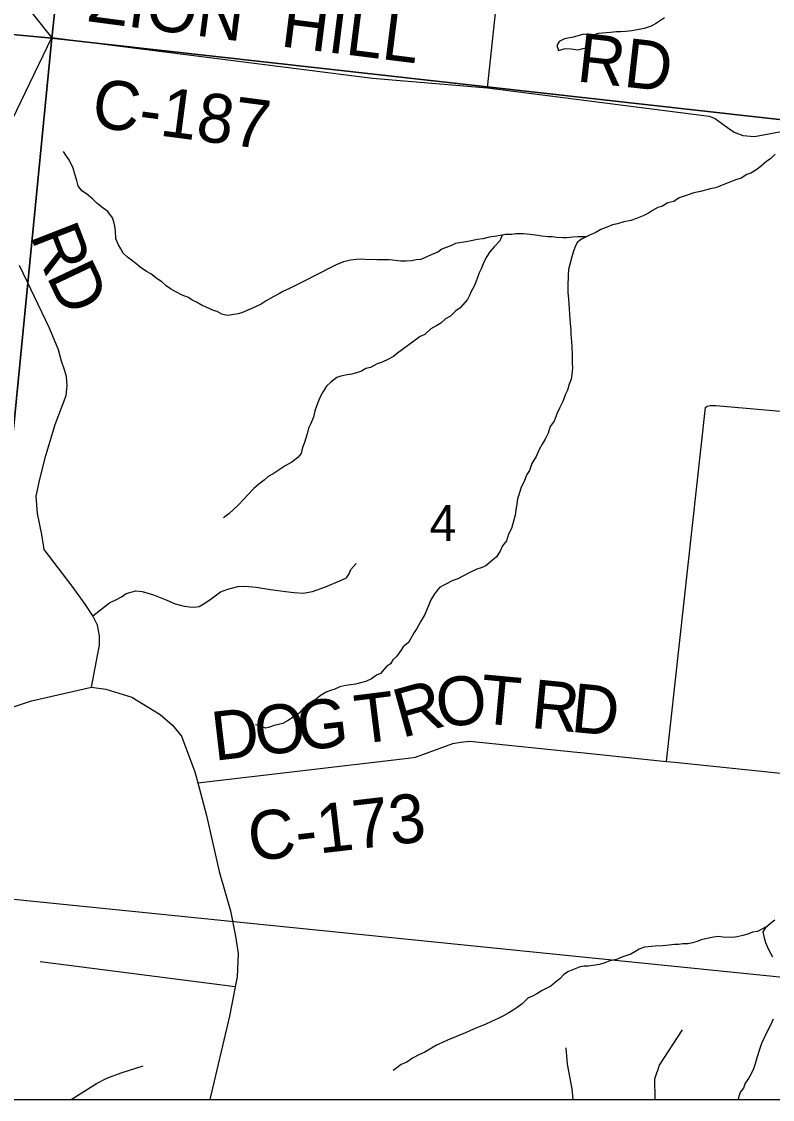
# Model space of a CAD drawing. Extents: x 0 to 34, y 0 to 22.
# Drawn here: x 4.14 to 5.013, y 14.1 to 15.353 of the extents above; entities that cross this region are included whole.
import ezdxf

# ---------------------------------------------------------------- set-up
doc = ezdxf.new("R2010")
doc.units = 0
for name, color, linetype in [('Default', 7, 'Continuous'), ('GM_X_County_Road', 7, 'Continuous'), ('GM_X_County_Road_Text', 7, 'Continuous'), ('GM_X_Minor_Lake', 7, 'Continuous'), ('GM_X_Minor_River', 7, 'Continuous'), ('GM_X_Section', 7, 'Continuous'), ('GM_X_Section_Text', 7, 'Continuous'), ('GM_X_State_Route', 7, 'Continuous'), ('GM_X_Township_Road', 7, 'Continuous'), ('SH_Data', 7, 'Continuous')]:
    doc.layers.add(name, color=color, linetype=linetype)

msp = doc.modelspace()

# ---------------------------------------------------------------- linework, layer by layer
at = {"layer": 'Default'}
msp.add_lwpolyline([(4.0529, 14.1), (5.0677, 14.1), (5.0822, 14.236), (4.0766, 14.3377)], close=True, dxfattribs=at)
at = {"layer": 'GM_X_County_Road'}
for points in [[(4.6816, 15.2761), (4.705, 15.4968)], [(4.1748, 15.3344), (4.0662, 15.4704)], [(4.1132, 15.2073), (4.1748, 15.3344)], [(4.1748, 15.3344), (4.5478, 15.2872), (4.6816, 15.2761)], [(4.6816, 15.2761), (4.9391, 15.2431), (4.9463, 15.2402), (4.9567, 15.2324), (4.9682, 15.2245), (4.9784, 15.2204), (4.992, 15.2193), (5.0649, 15.2329), (5.0706, 15.2347), (5.0765, 15.241), (5.0907, 15.2611), (5.0938, 15.2628), (5.0947, 15.2632), (5.0965, 15.2639), (5.0994, 15.2642), (5.1025, 15.2642), (5.132, 15.2596)], [(4.2209, 14.5791), (4.2266, 14.6097), (4.2303, 14.628), (4.2301, 14.639), (4.2279, 14.6513), (4.2225, 14.662), (4.2137, 14.6758), (4.1982, 14.6965), (4.166, 14.7393), (4.163, 14.7567), (4.1579, 14.781), (4.1566, 14.8012), (4.1609, 14.8212), (4.1676, 14.8487), (4.1787, 14.8845), (4.1914, 14.9184), (4.1924, 14.9301), (4.1918, 14.9404), (4.1895, 14.948), (4.1861, 14.9581), (4.1825, 14.9714), (4.1721, 14.9965), (4.1372, 15.0695)], [(4.3445, 14.4679), (4.5891, 14.4969), (4.5975, 14.4978), (4.6412, 14.5137), (4.65, 14.5154), (4.661, 14.5166), (4.7852, 14.5037), (4.7901, 14.5032)], [(4.7901, 14.5032), (4.8895, 14.4929), (4.8992, 14.4919)], [(4.8992, 14.4919), (5.026, 14.4788), (5.1037, 14.4707), (5.1182, 14.4692), (5.1285, 14.469), (5.1398, 14.4719), (5.1427, 14.4726)]]:
    msp.add_lwpolyline(points, dxfattribs=at)
at = {"layer": 'GM_X_Minor_Lake'}
for points in [[(4.7996, 15.3366), (4.7933, 15.3382), (4.781, 15.3347), (4.7711, 15.3327), (4.7649, 15.3298), (4.7622, 15.3253), (4.7639, 15.3192), (4.7716, 15.3217), (4.7788, 15.3211), (4.7863, 15.3202), (4.7913, 15.3212), (4.7986, 15.3232)], [(4.7986, 15.3232), (4.7996, 15.3366)]]:
    msp.add_lwpolyline(points, dxfattribs=at)
at = {"layer": 'GM_X_Minor_River'}
msp.add_line((4.9739, 14.1038), (4.9729, 14.1), dxfattribs=at)
for points in [[(4.8872, 15.3573), (4.8779, 15.3511), (4.8717, 15.3476), (4.8636, 15.3448), (4.8579, 15.3439), (4.8491, 15.3423), (4.8422, 15.3414), (4.8361, 15.3412), (4.8316, 15.341), (4.8243, 15.3401), (4.8194, 15.3399), (4.8102, 15.339), (4.8045, 15.3373), (4.7999, 15.3367), (4.7996, 15.3366)], [(4.2038, 15.1682), (4.2014, 15.1755), (4.1997, 15.1824), (4.1976, 15.187), (4.1944, 15.1928), (4.1911, 15.1975), (4.1882, 15.2021)], [(5.0161, 15.199), (5.011, 15.1938), (5.006, 15.1902), (4.9981, 15.1836), (4.9935, 15.1804), (4.9877, 15.1768), (4.983, 15.175), (4.9765, 15.1711), (4.9703, 15.169), (4.9622, 15.1659), (4.9576, 15.1638), (4.9464, 15.1596), (4.9403, 15.1587), (4.9292, 15.1556), (4.9212, 15.154), (4.9124, 15.1509), (4.9043, 15.1481), (4.8981, 15.1438), (4.8912, 15.1421), (4.8842, 15.1378), (4.8796, 15.1368), (4.8734, 15.1332), (4.8688, 15.1303), (4.8626, 15.1271), (4.8549, 15.124), (4.8483, 15.1219), (4.8399, 15.1203), (4.8326, 15.1179), (4.8269, 15.1166), (4.8196, 15.1134), (4.8134, 15.1114), (4.8065, 15.1074), (4.8007, 15.105), (4.7906, 15.1), (4.7859, 15.096), (4.7831, 15.0904), (4.781, 15.0848), (4.7797, 15.0795), (4.7775, 15.072), (4.7758, 15.0648), (4.7751, 15.058), (4.7747, 15.0455), (4.7748, 15.0382), (4.7757, 15.0306), (4.7759, 15.0245), (4.7765, 15.0196), (4.7766, 15.0123), (4.7772, 15.007), (4.7774, 15.0024), (4.7783, 14.9937), (4.7785, 14.9887), (4.779, 14.9811), (4.7795, 14.975), (4.7799, 14.9655), (4.78, 14.9556), (4.7802, 14.951), (4.78, 14.9461), (4.7786, 14.9374), (4.7765, 14.9314), (4.7744, 14.9246), (4.7723, 14.9198), (4.769, 14.9115), (4.7653, 14.9037), (4.7624, 14.8977), (4.7591, 14.8883), (4.7543, 14.8824), (4.7521, 14.8745), (4.7485, 14.8674), (4.7449, 14.8618), (4.7416, 14.8555), (4.7379, 14.8473), (4.7331, 14.8391), (4.7301, 14.8312), (4.7273, 14.8263), (4.7236, 14.8174), (4.7204, 14.8118), (4.7182, 14.8039), (4.7165, 14.7982), (4.7155, 14.7922), (4.7145, 14.785), (4.7136, 14.7793), (4.7092, 14.7635), (4.706, 14.7572), (4.7034, 14.7493), (4.699, 14.7434), (4.6962, 14.7374), (4.6918, 14.7307), (4.6871, 14.7267)], [(4.7959, 15.1026), (4.7866, 15.1028), (4.7805, 15.1022), (4.7736, 15.1017), (4.7691, 15.1015), (4.7619, 15.1021), (4.7566, 15.1027), (4.752, 15.1029), (4.7448, 15.1035), (4.7403, 15.1044), (4.7312, 15.1055), (4.7233, 15.1061), (4.7187, 15.1063), (4.7142, 15.1061), (4.7096, 15.1055), (4.7024, 15.1053), (4.6917, 15.1034), (4.6833, 15.1022), (4.676, 15.1005), (4.6695, 15.0996), (4.6645, 15.0983), (4.6584, 15.0973), (4.6539, 15.0967), (4.6489, 15.0958), (4.6443, 15.0948), (4.6397, 15.0927), (4.6335, 15.0902), (4.6285, 15.0885), (4.6235, 15.0849), (4.6188, 15.0831), (4.6115, 15.08), (4.6038, 15.0764), (4.5985, 15.0759), (4.5931, 15.0749), (4.5866, 15.0744), (4.5802, 15.0746), (4.5741, 15.0752), (4.567, 15.0758), (4.5575, 15.0761), (4.5529, 15.0759), (4.5393, 15.0764), (4.5336, 15.0766), (4.5286, 15.0764), (4.5221, 15.0755), (4.5141, 15.0735), (4.5056, 15.0703), (4.4968, 15.0661), (4.4886, 15.0618), (4.4801, 15.0572), (4.4705, 15.0522), (4.4612, 15.0476), (4.4558, 15.0451), (4.4504, 15.0422), (4.4442, 15.0394), (4.4396, 15.0369), (4.433, 15.0333), (4.4241, 15.0283), (4.4183, 15.0243), (4.4133, 15.0222), (4.4075, 15.0194), (4.4025, 15.0173), (4.3963, 15.0148), (4.3913, 15.0131), (4.384, 15.0119), (4.3787, 15.0113), (4.3723, 15.013), (4.3671, 15.0159), (4.3626, 15.0172), (4.3544, 15.0209), (4.3495, 15.0229), (4.3428, 15.0266), (4.3379, 15.029), (4.3335, 15.0322), (4.3264, 15.0351), (4.3189, 15.0388), (4.3126, 15.0424), (4.3078, 15.0456), (4.3026, 15.0504), (4.2974, 15.054), (4.29, 15.0596), (4.2848, 15.0624), (4.2774, 15.0676), (4.2726, 15.0716), (4.2674, 15.0755), (4.2626, 15.0791), (4.2578, 15.0838), (4.255, 15.0889), (4.2521, 15.0935), (4.2493, 15.1005), (4.2488, 15.1096), (4.2479, 15.1153), (4.2469, 15.1203), (4.2452, 15.1249), (4.2397, 15.132), (4.2346, 15.1359), (4.2272, 15.1419), (4.2224, 15.1466), (4.215, 15.1526), (4.2098, 15.1562), (4.2055, 15.162), (4.2038, 15.1682)], [(4.6985, 15.1046), (4.6957, 15.098), (4.6893, 15.091), (4.6842, 15.0851), (4.6806, 15.0799), (4.677, 15.0732), (4.674, 15.0657), (4.6716, 15.0608), (4.6699, 15.0555), (4.6678, 15.0499), (4.6654, 15.0447), (4.6625, 15.0391), (4.6605, 15.0346), (4.658, 15.0297), (4.6497, 15.0201), (4.6447, 15.0169), (4.6384, 15.0107), (4.6326, 15.0074), (4.6271, 15.0023), (4.6224, 14.9998), (4.6155, 14.9959), (4.6084, 14.9893), (4.603, 14.9868), (4.5956, 14.9814), (4.5898, 14.977), (4.5827, 14.9719), (4.5769, 14.9676), (4.5722, 14.9636), (4.5664, 14.9607), (4.5591, 14.9572), (4.5533, 14.9551), (4.5452, 14.9508), (4.5398, 14.9495), (4.5348, 14.9466), (4.529, 14.9445), (4.5237, 14.9432), (4.5183, 14.9422), (4.5107, 14.9406), (4.5061, 14.9392), (4.4994, 14.9338), (4.494, 14.929), (4.4903, 14.9231), (4.4871, 14.9175), (4.4846, 14.9111), (4.4825, 14.9059), (4.4805, 14.9006), (4.4791, 14.8931), (4.4757, 14.8848), (4.4733, 14.8803), (4.4716, 14.8739), (4.4686, 14.8638), (4.4661, 14.8578), (4.4647, 14.851), (4.4607, 14.8462), (4.4537, 14.8407), (4.446, 14.8365), (4.437, 14.8303), (4.432, 14.8274), (4.4262, 14.8242), (4.4215, 14.8198), (4.4153, 14.8151), (4.4098, 14.81), (4.4027, 14.803), (4.398, 14.7978), (4.3916, 14.7908), (4.3807, 14.7806), (4.3744, 14.7759)], [(4.6871, 14.7267), (4.6793, 14.7201), (4.6742, 14.718), (4.6689, 14.7163), (4.66, 14.712), (4.6534, 14.7088), (4.6469, 14.7053), (4.6411, 14.7032), (4.6314, 14.6982), (4.6256, 14.695), (4.6197, 14.6876), (4.6152, 14.6798), (4.6132, 14.6749), (4.6086, 14.6636), (4.6038, 14.6558), (4.5993, 14.6476), (4.5961, 14.6428), (4.5896, 14.6312), (4.5834, 14.6261), (4.5806, 14.6217), (4.5758, 14.6154), (4.5715, 14.611), (4.5687, 14.6065), (4.564, 14.6033), (4.5569, 14.5951), (4.5523, 14.593), (4.5464, 14.589), (4.5399, 14.5858), (4.5353, 14.5845), (4.528, 14.5828), (4.5219, 14.5819), (4.5165, 14.581), (4.5097, 14.5797), (4.5039, 14.5768), (4.4989, 14.5755), (4.4939, 14.5734), (4.4869, 14.5691), (4.4822, 14.5654), (4.4776, 14.5629), (4.4744, 14.5585), (4.4678, 14.5553), (4.4623, 14.549), (4.4553, 14.5443), (4.4487, 14.54), (4.4433, 14.5371), (4.4333, 14.5348), (4.4279, 14.5327), (4.4233, 14.5317), (4.4166, 14.5343), (4.4117, 14.5356)], [(5.0057, 14.3006), (4.9953, 14.2954), (4.9896, 14.2944), (4.9842, 14.2923), (4.9784, 14.2906), (4.9719, 14.2889), (4.9662, 14.2884), (4.9552, 14.2888), (4.9499, 14.2893), (4.9442, 14.2888), (4.935, 14.2868), (4.93, 14.2855), (4.9254, 14.2837), (4.9197, 14.282), (4.9147, 14.281), (4.9086, 14.2809), (4.9037, 14.2803), (4.8991, 14.2801), (4.8926, 14.2795), (4.885, 14.2786), (4.8763, 14.2782), (4.8641, 14.2771), (4.8579, 14.2746), (4.8529, 14.2714), (4.8482, 14.2689), (4.8436, 14.2672), (4.8375, 14.2655), (4.8313, 14.2626), (4.8237, 14.261), (4.8179, 14.2589), (4.8117, 14.2569), (4.8041, 14.2556), (4.7984, 14.255), (4.7938, 14.2548), (4.7893, 14.2542), (4.7816, 14.2511), (4.7758, 14.2486), (4.7703, 14.2454), (4.7656, 14.2402), (4.7605, 14.2362), (4.7551, 14.2318), (4.745, 14.2265), (4.7388, 14.2229), (4.7338, 14.22), (4.7284, 14.2176), (4.7217, 14.2113), (4.7159, 14.207), (4.7112, 14.2037), (4.7062, 14.2008), (4.7, 14.1973), (4.6938, 14.1941), (4.6868, 14.1909), (4.6787, 14.187), (4.6737, 14.1852), (4.6672, 14.1824), (4.6618, 14.18), (4.6549, 14.1772), (4.6487, 14.1747), (4.6425, 14.1719), (4.6356, 14.1691), (4.629, 14.1663), (4.6221, 14.1631), (4.6163, 14.1595), (4.6085, 14.1548), (4.6024, 14.1524), (4.5943, 14.1481), (4.5876, 14.1434), (4.5811, 14.1406), (4.576, 14.1369), (4.5716, 14.1335)], [(5.0155, 14.3083), (5.0104, 14.3047), (5.0042, 14.2992), (5.0017, 14.2948), (5.003, 14.2879), (5.0047, 14.2825), (5.0082, 14.2744), (5.0129, 14.2659)], [(5.0138, 14.1933), (5.0105, 14.1865), (5.006, 14.1776), (5.0032, 14.1716), (4.9999, 14.1649), (4.9969, 14.1558), (4.9956, 14.1506), (4.9939, 14.1457), (4.9926, 14.1412), (4.9909, 14.1355), (4.9881, 14.1299), (4.9848, 14.1243), (4.9812, 14.1188), (4.9791, 14.1131), (4.9756, 14.1087), (4.9739, 14.1038)]]:
    msp.add_lwpolyline(points, dxfattribs=at)
at = {"layer": 'GM_X_Section'}
for points in [[(3.2644, 16.338), (3.276, 16.3476), (3.3136, 16.3694), (3.3687, 16.3893), (4.2789, 16.3058), (4.1746, 15.3336), (3.1681, 15.4277)], [(5.2813, 16.2088), (5.1838, 15.2208), (4.1746, 15.3336), (4.2789, 16.3058)], [(4.1746, 15.3336), (4.0766, 14.3377), (3.0761, 14.4328), (3.1681, 15.4277)], [(5.1838, 15.2208), (5.0822, 14.236), (4.0766, 14.3377), (4.1746, 15.3336)]]:
    msp.add_lwpolyline(points, close=True, dxfattribs=at)
at = {"layer": 'GM_X_State_Route'}
for points in [[(2.1, 16.7408), (2.1, 14.1), (5.0661, 14.1), (5.1035, 14.4713), (5.1456, 14.8898), (5.1715, 15.1469), (5.2499, 15.926)], [(4.0744, 14.5377), (4.1512, 14.5633), (4.2209, 14.5791), (4.2376, 14.5769), (4.2677, 14.5678), (4.3009, 14.5473), (4.3151, 14.5352), (4.3257, 14.5224), (4.3411, 14.4807), (4.3445, 14.4679), (4.3547, 14.4299), (4.3694, 14.365), (4.3824, 14.3192), (4.3885, 14.2898), (4.3915, 14.2696), (4.3904, 14.2426), (4.3881, 14.2308), (4.3814, 14.1969), (4.3584, 14.1)]]:
    msp.add_lwpolyline(points, dxfattribs=at)
at = {"layer": 'GM_X_Township_Road'}
msp.add_line((4.3881, 14.2308), (4.1612, 14.26), dxfattribs=at)
for points in [[(4.8895, 14.4929), (4.9349, 14.9044), (4.9369, 14.9059), (4.9403, 14.9066), (4.9471, 14.9067), (5.1459, 14.8893), (5.1505, 14.8889)], [(4.2225, 14.662), (4.2418, 14.6774), (4.2507, 14.6814), (4.2559, 14.6844), (4.2613, 14.6883), (4.2723, 14.6913), (4.2799, 14.6903), (4.293, 14.6866), (4.3083, 14.6804), (4.3182, 14.676), (4.3286, 14.6735), (4.3347, 14.6726), (4.3397, 14.6723), (4.3459, 14.6731), (4.3509, 14.6759), (4.3586, 14.6809), (4.3709, 14.69), (4.3793, 14.6932), (4.3911, 14.6962), (4.3991, 14.6967), (4.4124, 14.6954), (4.429, 14.6926), (4.4464, 14.6906), (4.4564, 14.6891), (4.4671, 14.6884), (4.478, 14.6904), (4.493, 14.696), (4.5095, 14.7029), (4.5174, 14.7064), (4.5206, 14.7108), (4.5223, 14.7159), (4.5286, 14.723)], [(4.8766, 14.1), (4.8765, 14.1009), (4.8759, 14.124), (4.8813, 14.14), (4.9081, 14.1808)], [(4.7725, 14.1599), (4.7741, 14.1411), (4.7795, 14.1122), (4.7808, 14.1)], [(4.1971, 14.1), (4.215, 14.1113), (4.2266, 14.1186), (4.2386, 14.1247), (4.2554, 14.1311), (4.2811, 14.1392)]]:
    msp.add_lwpolyline(points, dxfattribs=at)
at = {"layer": 'SH_Data'}
msp.add_line((2.1, 14.1), (8.9, 14.1), dxfattribs=at)

# ---------------------------------------------------------------- texts
at = {"layer": 'GM_X_County_Road_Text'}
for s, height, rotation, p in [('ZION', 0.05682, 352.4824, (4.2152, 15.3535)), ('HILL', 0.05682, 352.8364, (4.4396, 15.3243)), ('RD', 0.05682, 353.5502, (4.784, 15.2836)), ('C-187', 0.05682, 352.5328, (4.2195, 15.231)), ('R', 0.0568, 291.3066, (4.1493, 15.1045)), ('D', 0.0568, 295.3645, (4.168, 15.0571)), ('R', 0.0568, 15.4761, (4.5819, 14.5199)), ('O', 0.0568, 6.52, (4.6246, 14.5319)), ('T', 0.0568, 354.7642, (4.6712, 14.5376)), ('R', 0.0568, 354.457, (4.7308, 14.532)), ('T', 0.0568, 7.1672, (4.5309, 14.5129)), ('D', 0.0568, 354.4634, (4.7773, 14.5275)), ('O', 0.0568, 6.5861, (4.4136, 14.4993)), ('G', 0.0568, 6.589, (4.4632, 14.505)), ('D', 0.0568, 6.5897, (4.3639, 14.4936)), ('C-173', 0.05682, 6.614, (4.4062, 14.3766))]:
    msp.add_text(s, height=height, rotation=rotation, dxfattribs=at).set_placement(p)
at = {"layer": 'GM_X_Section_Text'}
msp.add_text('4', height=0.0419, rotation=0, dxfattribs=at).set_placement((4.614, 14.7492))

doc.saveas('drawing.dxf')
